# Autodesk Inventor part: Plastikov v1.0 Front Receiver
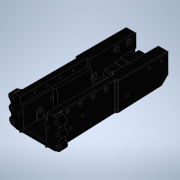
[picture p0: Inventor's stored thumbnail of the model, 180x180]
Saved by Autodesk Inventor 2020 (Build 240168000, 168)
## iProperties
Created: 2020-05
Part Number: Plastikov v1.0 Front Receiver
Material: Steel
Document SubType Name: Modeling
Designer: Iv. Tr.
Density: 7.85 g/cm^3
Appearance: Default
Title: D:\Downloads\Plastikov-v1-2 (2)\STEP\Plastikov v1.0 Front Receiver.stp
Author: johne
Sending System: Autodesk Inventor 2020
Preprocessor: ST-DEVELOPER v18
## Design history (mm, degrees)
feature "Solid2"
body "Solid1"
